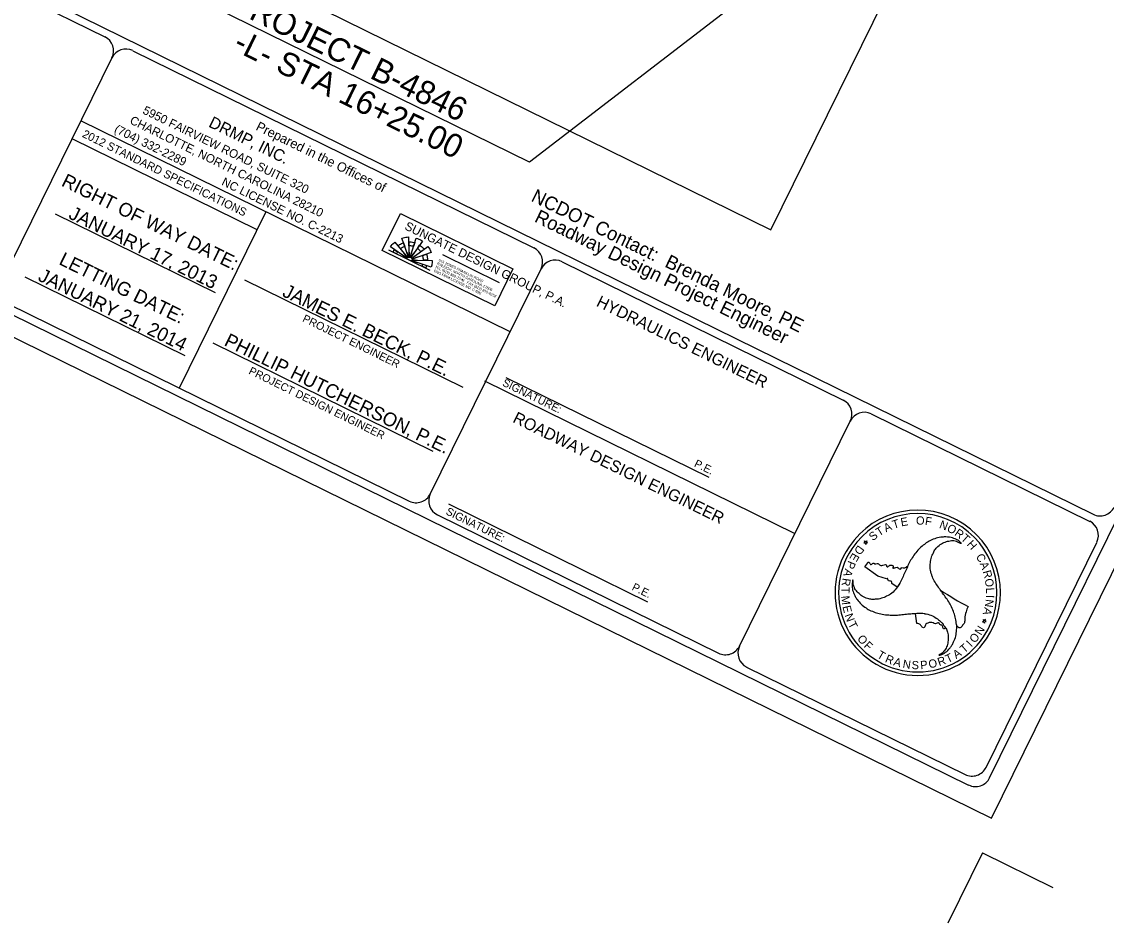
# Model space of a CAD drawing. Extents: x 1428128 to 1430390, y 857947 to 859822.
# Drawn here: x 1429306 to 1429997, y 857947 to 858523 of the extents above; entities that cross this region are included whole.
import ezdxf

# ---------------------------------------------------------------- set-up
doc = ezdxf.new("R2010")
doc.units = 0
for name, color, linetype in [('Exist Horizontal Alignment Station Label', 7, 'Continuous'), ('Old_Level_1', 7, 'Continuous'), ('Old_Level_43', 7, 'Continuous'), ('Old_Level_51', 7, 'Continuous'), ('Sheet Data Field CELL', 7, 'Continuous'), ('Sheet Plot Border Inside CELL', 7, 'Continuous'), ('Sheet Title CELL', 7, 'Continuous')]:
    doc.layers.add(name, color=color, linetype=linetype)

msp = doc.modelspace()

# ---------------------------------------------------------------- linework, layer by layer
at = {"layer": 'Exist Horizontal Alignment Station Label'}
for q in [(1429896.08, 857947.41), (1429963.02, 857970.2)]:
    msp.add_line((1429918.16, 857992.27), q, dxfattribs=at)
at = {"layer": 'Old_Level_1'}
for p, q in [((1429629.26, 858432.82), (1429353.02, 858568.75)), ((1429804.75, 858567.76), (1429629.26, 858432.82))]:
    msp.add_line(p, q, dxfattribs=at)
at = {"layer": 'Old_Level_51'}
for p, q in [((1429539.54, 858376.99), (1429565.89, 858364.03)), ((1429544.17, 858376.41), (1429544.17, 858376.41)), ((1429551.04, 858375.5), (1429552.11, 858372.31)), ((1429552.46, 858379.54), (1429552.46, 858379.54)), ((1429552.66, 858372.4), (1429552.55, 858375.77)), ((1429553.29, 858372.32), (1429554.32, 858375.52)), ((1429560.05, 858375.81), (1429560.05, 858375.81)), ((1429551.15, 858371.59), (1429548.39, 858373.5)), ((1429551.53, 858371.99), (1429549.43, 858374.62)), ((1429550.01, 858373.91), (1429550.01, 858373.91)), ((1429553.79, 858372.07), (1429555.7, 858374.84)), ((1429554.25, 858371.62), (1429556.98, 858373.58)), ((1429557.69, 858372.23), (1429554.51, 858371.13)), ((1429554.52, 858369.93), (1429557.73, 858368.91)), ((1429556.55, 858370.44), (1429554.61, 858370.48)), ((1429554.61, 858370.48), (1429557.97, 858370.42)), ((1429573.98, 858373.92), (1429610.04, 858356.18))]:
    msp.add_line(p, q, dxfattribs=at)
for points in [[(1429547.03, 858400.13), (1429618.81, 858364.81), (1429607.25, 858341.3), (1429535.47, 858376.62)], [(1429552.11, 858372.31), (1429548.04, 858384.43), (1429548.84, 858384.68), (1429549.7, 858384.88), (1429550.52, 858385.03), (1429551.41, 858385.14), (1429552.25, 858385.19), (1429552.66, 858372.4)], [(1429553.29, 858372.32), (1429557.2, 858384.5), (1429557.97, 858384.23), (1429558.82, 858383.87), (1429559.51, 858383.53), (1429560.33, 858383.07), (1429561.06, 858382.6), (1429553.79, 858372.07)], [(1429551.15, 858371.59), (1429540.63, 858378.85), (1429541.09, 858379.48), (1429541.82, 858380.36), (1429542.32, 858380.88), (1429543, 858381.52), (1429543.54, 858381.98), (1429551.53, 858371.99)], [(1429542.31, 858375.63), (1429542.54, 858376.08), (1429542.83, 858376.59), (1429543.17, 858377.1), (1429545.28, 858375.64), (1429545.05, 858375.27), (1429544.82, 858374.89), (1429544.62, 858374.49)], [(1429545.47, 858379.57), (1429546.05, 858380), (1429546.54, 858380.33), (1429547.14, 858380.69), (1429547.71, 858380.98), (1429548.32, 858381.25), (1429549.02, 858381.51), (1429549.84, 858379.07), (1429549.25, 858378.85), (1429548.76, 858378.63), (1429548.28, 858378.37), (1429547.77, 858378.06), (1429547.39, 858377.8), (1429547.07, 858377.56)], [(1429552.35, 858382.11), (1429552.97, 858382.11), (1429553.88, 858382.05), (1429554.82, 858381.92), (1429555.64, 858381.74), (1429556.26, 858381.56), (1429555.47, 858379.11), (1429554.89, 858379.28), (1429554.32, 858379.4), (1429553.71, 858379.48), (1429553.05, 858379.53), (1429552.43, 858379.54)], [(1429554.25, 858371.62), (1429564.63, 858379.1), (1429565.17, 858378.3), (1429565.73, 858377.32), (1429566.06, 858376.65), (1429566.35, 858375.99), (1429566.6, 858375.3), (1429554.51, 858371.13)], [(1429559.31, 858380.06), (1429559.88, 858379.64), (1429560.5, 858379.11), (1429561.1, 858378.53), (1429561.61, 858377.96), (1429562.13, 858377.3), (1429560.04, 858375.79), (1429559.75, 858376.17), (1429559.35, 858376.64), (1429558.74, 858377.24), (1429558.29, 858377.61), (1429557.85, 858377.94)], [(1429551.01, 858371.35), (1429551.08, 858371.47), (1429551.15, 858371.58), (1429551.35, 858371.82), (1429551.53, 858371.99), (1429551.69, 858372.1), (1429551.85, 858372.2), (1429551.99, 858372.26), (1429552.11, 858372.31), (1429552.39, 858372.38), (1429552.66, 858372.4), (1429552.83, 858372.4), (1429553.02, 858372.38), (1429553.18, 858372.35), (1429553.29, 858372.32), (1429553.56, 858372.21), (1429553.79, 858372.07), (1429553.93, 858371.97), (1429554.03, 858371.87), (1429554.14, 858371.76), (1429554.25, 858371.62), (1429554.4, 858371.38), (1429554.51, 858371.13), (1429554.55, 858370.98), (1429554.59, 858370.81), (1429554.61, 858370.67), (1429554.61, 858370.48), (1429554.58, 858370.18), (1429554.52, 858369.93), (1429554.47, 858369.79), (1429554.42, 858369.67)], [(1429554.6, 858370.47), (1429567.4, 858370.25), (1429567.38, 858369.58), (1429567.3, 858368.79), (1429567.18, 858367.92), (1429567.04, 858367.25), (1429566.7, 858366.02), (1429554.52, 858369.93)], [(1429563.68, 858374.29), (1429563.89, 858373.65), (1429564.06, 858372.96), (1429564.19, 858372.26), (1429564.29, 858371.3), (1429564.32, 858370.3), (1429561.74, 858370.35), (1429561.73, 858371), (1429561.66, 858371.75), (1429561.57, 858372.3), (1429561.45, 858372.79), (1429561.25, 858373.45)], [(1429563.77, 858366.97), (1429563.46, 858366.13), (1429563.14, 858365.41), (1429560.82, 858366.52), (1429561.09, 858367.12), (1429561.31, 858367.75)]]:
    msp.add_lwpolyline(points, close=True, dxfattribs=at)
for start, end in [(153.80011, 333.80011), (333.80011, 153.80011)]:
    msp.add_arc((1429586.51, 858357.88), 0.082, start, end, dxfattribs=at)
at = {"layer": 'Sheet Data Field CELL'}
msp.add_lwpolyline([(1429452.45, 858991.29), (1429278.61, 858637.99), (1429783.32, 858389.64), (1429957.17, 858742.94)], dxfattribs=at)
at = {"layer": 'Sheet Plot Border Inside CELL'}
msp.add_lwpolyline([(1428428.74, 858750.16), (1429924.03, 858014.39), (1430389.86, 858961.09), (1428894.57, 859696.85)], close=True, dxfattribs=at)
at = {"layer": 'Sheet Title CELL'}
for p, q in [((1428714.68, 858835.22), (1429988.78, 858208.28)), ((1429017.53, 858680.61), (1429358.49, 858512.84)), ((1429376.44, 858504.02), (1429632.16, 858378.19)), ((1429363.05, 858499.46), (1429292.41, 858355.9)), ((1429616.95, 858324.64), (1429343.3, 858459.31)), ((1429455.69, 858389.78), (1429337.67, 858447.87)), ((1429421.69, 858406.52), (1429421.69, 858406.52)), ((1429429.19, 858349.5), (1429327.13, 858399.73)), ((1429461.33, 858401.23), (1429406.03, 858288.85)), ((1429378.13, 858374.61), (1429378.13, 858374.61)), ((1429650.1, 858369.36), (1429829.35, 858281.16)), ((1429566.07, 858221.23), (1429636.71, 858364.79)), ((1429409.86, 858309.31), (1429307.8, 858359.53)), ((1429447.65, 858357.81), (1429586.86, 858289.3)), ((1429427.47, 858317.58), (1429567.67, 858248.6)), ((1429600.6, 858293.44), (1429798.6, 858196.01)), ((1429614.35, 858295.58), (1429743.78, 858231.89)), ((1429847.3, 858272.33), (1429986.58, 858203.8)), ((1429763.27, 858124.21), (1429833.91, 858267.77)), ((1429577.72, 858214.9), (1429704.68, 858152.41)), ((1429842.53, 858189.94), (1429843.24, 858190.51)), ((1429843.42, 858190), (1429842.53, 858189.94)), ((1429843.24, 858190.51), (1429842.93, 858191.38)), ((1429842.93, 858191.38), (1429843.7, 858190.86)), ((1429843.74, 858189.13), (1429843.42, 858190)), ((1429843.7, 858190.86), (1429844.38, 858191.43)), ((1429843.99, 858190.01), (1429843.74, 858189.13)), ((1429844.92, 858190.05), (1429843.99, 858190.01)), ((1429844.38, 858191.43), (1429844.17, 858190.55)), ((1429844.17, 858190.55), (1429844.92, 858190.05)), ((1429904.8, 858189.86), (1429904.66, 858189.83)), ((1429843.3, 858174.79), (1429845.16, 858177.37)), ((1429851.41, 858168.92), (1429843.3, 858174.79)), ((1429857.11, 858167.14), (1429851.41, 858168.92)), ((1429863.85, 858161.78), (1429860.41, 858164.14)), ((1429891.49, 858159.82), (1429891.49, 858159.82)), ((1429876.43, 858138.65), (1429875.42, 858145.1)), ((1429875.42, 858145.1), (1429875.42, 858145.1)), ((1429918.92, 858140.27), (1429918.21, 858139.69)), ((1429919.35, 858140.62), (1429918.59, 858141.12)), ((1429918.59, 858141.12), (1429918.92, 858140.27)), ((1429920.05, 858141.17), (1429919.35, 858140.62)), ((1429919.84, 858140.29), (1429920.05, 858141.17)), ((1429920.6, 858139.82), (1429919.84, 858140.29)), ((1429918.21, 858139.69), (1429919.09, 858139.74)), ((1429919.09, 858139.74), (1429919.41, 858138.89)), ((1429919.41, 858138.89), (1429919.67, 858139.76)), ((1429919.67, 858139.76), (1429920.6, 858139.82)), ((1429920.76, 858128.96), (1429920.76, 858128.96))]:
    msp.add_line(p, q, dxfattribs=at)
for points in [[(1429922.77, 858040.15), (1430368.69, 858946.37)], [(1428581.44, 858689.01), (1429909.38, 858035.58)], [(1429296.97, 858342.51), (1429552.68, 858216.67)], [(1429570.63, 858207.85), (1429749.88, 858119.65)], [(1429920.49, 858046.85), (1429991.13, 858190.41)], [(1429767.83, 858110.82), (1429907.11, 858042.29)]]:
    msp.add_lwpolyline(points, dxfattribs=at)
for centre, radius, start, end in [((1429354.1, 858503.91), 10, 333.80011, 63.80011), ((1429372.05, 858495.08), 10, 63.80011, 153.80011), ((1429627.77, 858369.26), 10, 333.80011, 63.80011), ((1429645.71, 858360.43), 10, 63.80011, 153.80011), ((1429824.94, 858272.19), 10, 333.80011, 63.80011), ((1429842.88, 858263.36), 10, 63.80011, 153.80011), ((1429557.13, 858225.69), 10, 243.80011, 333.80011), ((1429575.07, 858216.86), 10, 153.80011, 243.80011), ((1429876.94, 858158.26), 52.72, 326.22125, 146.22125), ((1429993.22, 858217.29), 10, 243.80011, 333.80011), ((1429876.94, 858158.26), 50.52, 326.22125, 146.22125), ((1429982.18, 858194.86), 10, 333.80011, 63.80011), ((1429876.94, 858158.26), 52.72, 146.22125, 326.22125), ((1429876.94, 858158.26), 50.52, 146.22125, 326.22125), ((1430041.49, 858393.82), 277.94, 231.89974, 231.99933), ((1430041.49, 858393.82), 277.94, 237.33879, 241.5448), ((1429754.32, 858128.68), 10, 243.80011, 333.80011), ((1429772.27, 858119.85), 10, 153.80011, 243.80011), ((1429911.54, 858051.3), 10, 243.80011, 333.80011), ((1429913.82, 858044.61), 10, 243.80011, 333.80011)]:
    msp.add_arc(centre, radius, start, end, dxfattribs=at)
for points in [[(1429904.66, 858189.83), (1429903.85, 858190.75), (1429900.86, 858192.57), (1429897.27, 858193.61), (1429896.91, 858193.64), (1429894.91, 858193.85), (1429892.56, 858193.73), (1429888.68, 858193.07), (1429885.01, 858191.52), (1429883.49, 858190.83), (1429881.98, 858189.73), (1429878.94, 858187.29), (1429876.44, 858184.64), (1429873.91, 858181.28), (1429871.91, 858178.18), (1429870.32, 858174.71), (1429868.75, 858171.19), (1429867.16, 858167.82), (1429865.48, 858164.38), (1429863.4, 858161.24), (1429863.2, 858160.98), (1429860.41, 858158.01), (1429857.1, 858155.99), (1429853.72, 858154.7), (1429851.94, 858154.26), (1429849.71, 858154.1), (1429848.43, 858153.99), (1429845.77, 858154.31), (1429842.3, 858155.61), (1429839.48, 858157.75), (1429837.32, 858160.15), (1429836.02, 858163.14), (1429835.62, 858166.45)], [(1429890.42, 858118.35), (1429891.57, 858118.6), (1429894.67, 858120.26), (1429897.37, 858122.86), (1429897.61, 858123.13), (1429898.75, 858124.79), (1429899.84, 858126.9), (1429901.25, 858130.56), (1429901.69, 858134.52), (1429901.88, 858136.18), (1429901.67, 858138.06), (1429901.08, 858141.9), (1429900.05, 858145.39), (1429898.38, 858149.25), (1429896.68, 858152.51), (1429894.49, 858155.67), (1429892.23, 858158.76), (1429890.13, 858161.8), (1429887.94, 858165.03), (1429886.29, 858168.37), (1429886.18, 858168.69), (1429884.97, 858172.62), (1429884.89, 858176.49), (1429885.44, 858180.05), (1429885.98, 858181.77), (1429886.97, 858183.8), (1429887.48, 858185), (1429889.12, 858187.1), (1429891.99, 858189.49), (1429895.21, 858190.85), (1429898.37, 858191.5), (1429901.63, 858191.12), (1429904.66, 858189.83), (1429904.8, 858189.86)], [(1429845.16, 858177.37), (1429845.23, 858177.68), (1429845.87, 858177.67), (1429846.76, 858176.33), (1429847.74, 858176.45), (1429848.07, 858177), (1429848.92, 858177.2), (1429849.65, 858176.47), (1429851.07, 858176.93), (1429851.88, 858176.63), (1429853.36, 858175.64), (1429856.3, 858176.23), (1429857.11, 858175.84), (1429856.98, 858175.25), (1429857.37, 858174.86), (1429859.1, 858175.81), (1429859.43, 858175.89), (1429861.17, 858175.51), (1429861.36, 858175.01), (1429861.03, 858174.29), (1429861.14, 858174.03), (1429861.81, 858174.05), (1429862.94, 858174.42), (1429864.47, 858174.25), (1429865.65, 858173.23), (1429866.57, 858174.14), (1429868.76, 858174.14), (1429869.48, 858174.54), (1429869.97, 858175.11)], [(1429870.36, 858174.8), (1429870.32, 858174.71), (1429868.75, 858171.19), (1429867.16, 858167.82), (1429865.48, 858164.38), (1429863.84, 858161.79)], [(1429835.62, 858166.45), (1429835.27, 858165.26), (1429835.17, 858161.76), (1429836.05, 858158.12), (1429836.21, 858157.83), (1429837.03, 858155.94), (1429838.32, 858153.99), (1429840.82, 858150.93), (1429843.99, 858148.58), (1429845.33, 858147.59), (1429847.12, 858146.8), (1429850.68, 858145.44), (1429854.2, 858144.57), (1429858.41, 858144.07), (1429862.06, 858143.9), (1429865.9, 858144.24), (1429869.72, 858144.68), (1429873.44, 858144.95), (1429877.27, 858145.19), (1429881.03, 858144.99), (1429881.4, 858144.91), (1429885.37, 858143.98), (1429888.73, 858142.15), (1429891.52, 858139.91), (1429892.85, 858138.55), (1429894.03, 858136.69), (1429894.84, 858135.64), (1429895.85, 858133.18), (1429896.44, 858129.53), (1429896.03, 858126.05), (1429895.01, 858122.95), (1429893.06, 858120.32), (1429890.42, 858118.35)], [(1429860.41, 858164.14), (1429860.5, 858165), (1429859.95, 858165.65), (1429858.72, 858165.78), (1429858.06, 858166.28), (1429857.67, 858167.32), (1429857.11, 858167.14)], [(1429901.87, 858136.86), (1429901.67, 858138.06), (1429901.08, 858141.9), (1429900.05, 858145.39), (1429898.38, 858149.25), (1429896.68, 858152.51), (1429894.49, 858155.67), (1429892.23, 858158.76), (1429891.49, 858159.82)], [(1429909.05, 858149.45), (1429907.71, 858146.11), (1429906.94, 858141.64), (1429906.67, 858139.1), (1429905.56, 858137.49), (1429903.89, 858135.81), (1429901.89, 858136.86)], [(1429875.42, 858145.1), (1429877.27, 858145.19), (1429881.03, 858144.99), (1429881.4, 858144.91), (1429885.37, 858143.98), (1429888.73, 858142.15), (1429891.52, 858139.91), (1429892.85, 858138.55), (1429894.03, 858136.69), (1429894.78, 858135.7)], [(1429894.75, 858135.7), (1429893.84, 858135.2), (1429893.14, 858135.59), (1429892.6, 858137.29), (1429891, 858137.95), (1429890.6, 858138.76), (1429890.18, 858139.06), (1429888.29, 858138.46), (1429886.68, 858139.09), (1429883.29, 858138.93), (1429882.17, 858138.27), (1429880.93, 858136.05), (1429880.09, 858136.01), (1429879.49, 858136.57), (1429878.45, 858138.05), (1429876.43, 858138.65)]]:
    msp.add_spline(points, degree=3, dxfattribs=at)

# ---------------------------------------------------------------- texts
at = {"layer": 'Old_Level_43'}
for s, height, p in [('5950 FAIRVIEW ROAD, SUITE 320', 5.4725, (1429382.22, 858464.16)), ('CHARLOTTE, NORTH CAROLINA 28210', 5.4725, (1429373.98, 858457.8)), ('DRMP, INC.', 7.5, (1429424.18, 858455.76)), ('(704) 332-2289', 5.4725, (1429364.07, 858452.26)), ('NC LICENSE NO. C-2213', 5.4725, (1429432.56, 858418.55))]:
    msp.add_text(s, height=height, rotation=333.80011, dxfattribs=at).set_placement(p)
at = {"layer": 'Old_Level_51'}
for s, height, p in [('SUNGATE DESIGN GROUP, P.A.', 5.5473, (1429549.28, 858390.28)), ('RALEIGH, NORTH CAROLINA 27606', 1.6671, (1429570.15, 858367.74)), ('915 JONES FRANKLIN ROAD', 1.6671, (1429571.23, 858369.94)), ('ENG FIRM LICENSE NO. C-890', 1.6671, (1429568.18, 858363.07)), ('TEL (919) 859-2243   FAX (919) 859-6258', 1.6671, (1429568.88, 858365.55))]:
    msp.add_text(s, height=height, rotation=333.80011, dxfattribs=at).set_placement(p)
at = {"layer": 'Sheet Data Field CELL'}
for s, height, p in [('END TIP PROJECT B-4846', 15, (1429361.82, 858568.06)), ('-L- STA 16+25.00', 15, (1429439.65, 858504.69)), ('Prepared in the Offices of', 5.9994, (1429454.39, 858453.69)), ('NCDOT Contact:  Brenda Moore, PE', 8.7501, (1429629.81, 858408.38)), ('JANUARY 17, 2013', 8.7501, (1429334.84, 858397.35)), ('Roadway Design Project Engineer', 8.7501, (1429631.9, 858395.19)), ('JANUARY 21, 2014', 8.7501, (1429315.38, 858357.68)), ('JAMES E. BECK, P.E.', 8.7501, (1429471.11, 858347.7)), ('PHILLIP HUTCHERSON, P.E.', 8.7501, (1429434.07, 858316.3))]:
    msp.add_text(s, height=height, rotation=333.80011, dxfattribs=at).set_placement(p)
at = {"layer": 'Sheet Title CELL'}
for s, height, rotation, p in [('2012 STANDARD SPECIFICATIONS', 5.2, 333.80011, (1429343.71, 858449.19)), ('RIGHT OF WAY DATE: ', 8.7498, 333.80011, (1429330.32, 858418.1)), ('LETTING DATE:', 8.7498, 333.80011, (1429328.69, 858368.03)), (' HYDRAULICS ENGINEER', 7.5, 333.80011, (1429668.9, 858342.64)), ('PROJECT ENGINEER', 4.9995, 333.80011, (1429484.14, 858331.5)), ('PROJECT DESIGN ENGINEER', 4.9995, 333.80011, (1429449.88, 858298.13)), ('SIGNATURE:', 4.999, 333.80011, (1429611.59, 858290.59)), ('ROADWAY DESIGN ENGINEER', 7.4994, 333.80011, (1429618.13, 858267.29)), ('P.E.', 4.999, 333.80011, (1429733.95, 858239)), ('SIGNATURE:', 4.999, 333.80011, (1429575.57, 858208.49)), ('A', 5.27, 24.54903, (1429856.65, 858196.77)), ('T', 5.24, 17.49381, (1429861.6, 858199.02)), ('E', 5.24, 10.37818, (1429866.51, 858200.55)), ('O', 5.26, 358.4388, (1429875.75, 858201.77)), ('F', 5.27, 351.29196, (1429881.31, 858201.59)), ('N', 5.26, 339.20502, (1429890.26, 858199.72)), ('S', 5.25, 37.9775, (1429848.29, 858191.07)), ('T', 5.27, 31.60134, (1429852.24, 858194.14)), ('O', 5.27, 331.70691, (1429895.06, 858197.87)), ('R', 5.26, 325.09698, (1429899.95, 858195.23)), ('T', 5.27, 318.44735, (1429904.08, 858192.36)), ('D', 5.26, 234.07424, (1429839.01, 858189)), ('H', 5.25, 311.36263, (1429907.91, 858188.92)), ('E', 5.23, 240.36213, (1429835.51, 858184.08)), ('C', 5.24, 299.02028, (1429913.82, 858181.46)), ('P', 5.26, 247.89453, (1429832.78, 858179.07)), ('A', 5.25, 291.52325, (1429916.35, 858176.86)), ('A', 5.25, 254.4871, (1429830.67, 858173.86)), ('R', 5.25, 285.15931, (1429918.33, 858171.85)), ('P.E.', 4.999, 333.80011, (1429694.21, 858160.25)), ('T', 5.25, 268.20627, (1429828.27, 858162.1)), ('R', 5.26, 261.55574, (1429829.07, 858167.85)), ('O', 5.27, 278.0397, (1429919.63, 858166.99)), ('L', 5.24, 271.80603, (1429920.42, 858161.45)), ('M', 5.24, 275.44131, (1429828.17, 858156.13)), ('I', 5.26, 267.81668, (1429920.46, 858156.91)), ('E', 5.24, 282.90808, (1429828.92, 858149.49)), ('A', 5.26, 254.6846, (1429919.58, 858149.24)), ('N', 5.25, 262.11658, (1429920.33, 858154.34)), ('N', 5.27, 289.87963, (1429830.25, 858143.97)), ('T', 5.25, 296.72163, (1429832.32, 858138.42)), ('N', 5.26, 58.42938, (1429917.33, 858130.73)), ('O', 5.25, 310.02531, (1429838.02, 858128.76)), ('F', 5.25, 317.19054, (1429842.17, 858123.95)), ('I', 5.27, 46.04573, (1429911.08, 858123.29)), ('O', 5.24, 51.18136, (1429913.4, 858125.74)), ('T', 5.24, 330.09977, (1429850.51, 858117.17)), ('T', 5.24, 25.22436, (1429896.06, 858113.32)), ('A', 5.27, 33.3114, (1429901.41, 858115.94)), ('T', 5.25, 40.39583, (1429906.58, 858119.42)), ('R', 5.26, 337.05639, (1429855.71, 858114.25)), ('A', 5.24, 343.80952, (1429861.09, 858112.07)), ('N', 5.24, 350.84115, (1429867.08, 858110.43)), ('S', 5.23, 358.05162, (1429872.97, 858109.59)), ('P', 5.25, 5.24347, (1429878.78, 858109.43)), ('O', 5.27, 11.93546, (1429884.38, 858109.98)), ('R', 5.27, 19.12457, (1429890.59, 858111.34))]:
    msp.add_text(s, height=height, rotation=rotation, dxfattribs=at).set_placement(p)

doc.saveas('drawing.dxf')
